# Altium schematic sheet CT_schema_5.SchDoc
size 364 x 245 mm
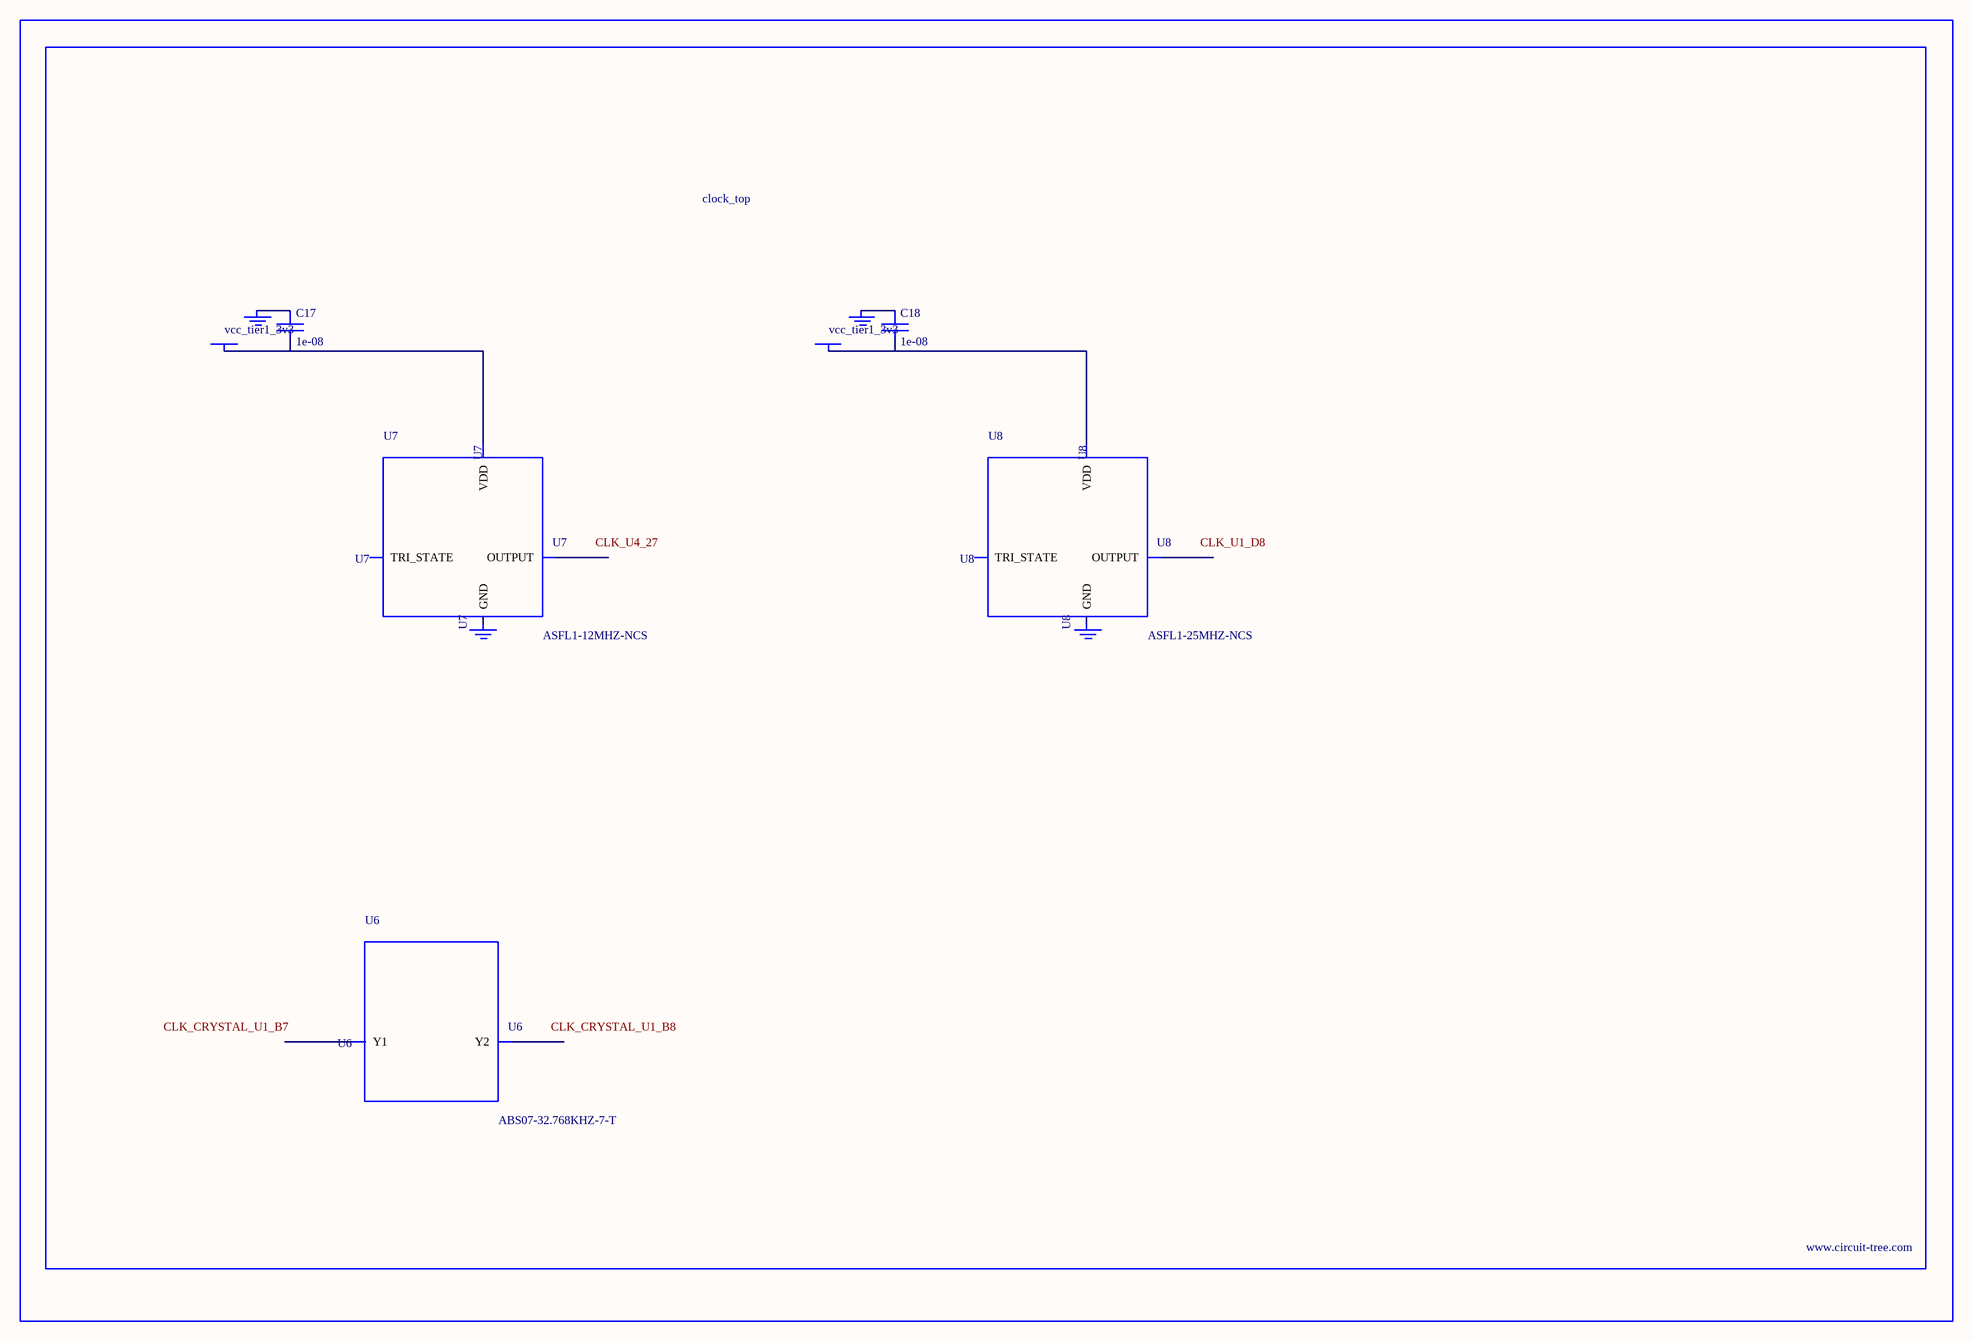
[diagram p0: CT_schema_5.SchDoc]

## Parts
BORDER4  (no value)
C17  1e-08  [C0402]
C18  1e-08  [C0402]
GND_INSTANCE_4_0  (no value)
GND_INSTANCE_4_1  (no value)
GND_INSTANCE_4_2  (no value)
GND_INSTANCE_4_3  (no value)
POWER_INSTANCE_4_0  vcc_tier1_3v3
POWER_INSTANCE_4_1  vcc_tier1_3v3
U6  ABS07-32.768KHZ-7-T  [ABS07-32.768KHZ-7-T]
U7  ASFL1-12MHZ-NCS  [ASFL1]
U8  ASFL1-25MHZ-NCS  [ASFL1]

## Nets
NetC17_1: C17.1 GND_INSTANCE_4_0.0(GND)
NetC17_2: C17.2 POWER_INSTANCE_4_0.0(PWR) U7.4(VDD)
NetC18_1: C18.1 GND_INSTANCE_4_2.0(GND)
NetC18_2: C18.2 POWER_INSTANCE_4_1.0(PWR) U8.4(VDD)

Not connected (* = marked no-connect by the designer): GND_INSTANCE_4_1 0(GND); GND_INSTANCE_4_3 0(GND); U6 1(Y1) 2(Y2); U7 1(TRI_STATE) 2(GND) 3(OUTPUT); U8 1(TRI_STATE) 2(GND) 3(OUTPUT)

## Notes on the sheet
- Labels drawn without touching a wire or pin: CLK_CRYSTAL_U1_B7, CLK_CRYSTAL_U1_B8, CLK_U1_D8, CLK_U4_27

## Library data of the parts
BORDER4 = BORDER_PAGE4
C17 C18 = C0402C103K3RAC
GND_INSTANCE_4_0-GND_INSTANCE_4_3 = GND
POWER_INSTANCE_4_0 POWER_INSTANCE_4_1 = PWR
